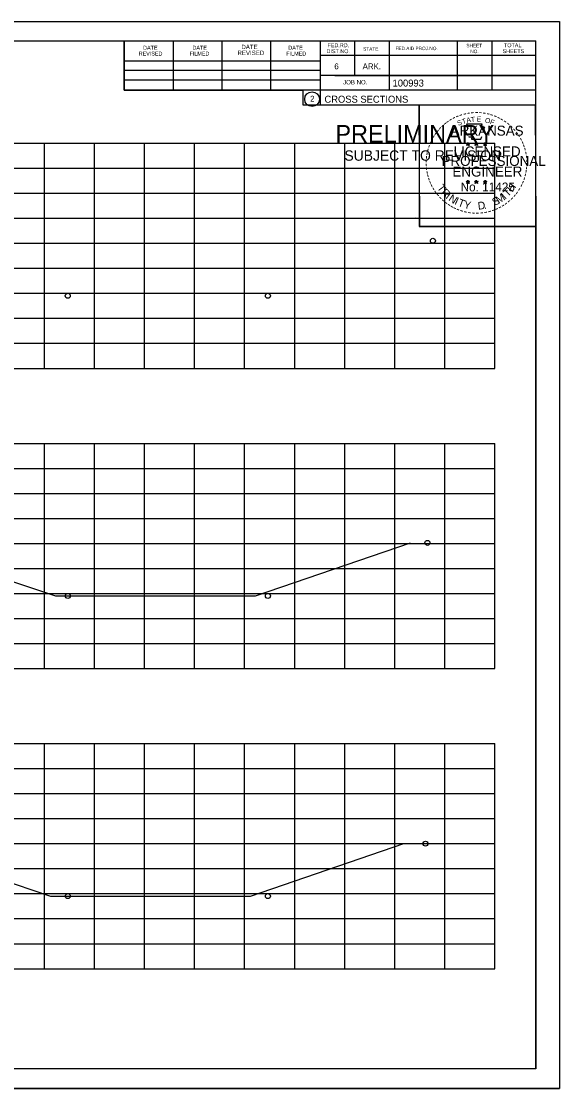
# Model space of a CAD drawing. Extents: x 4667 to 1632277, y -2100 to 724501.
# Drawn here: x 6194.9 to 6302.5, y -1537.1 to -1323.8 of the extents above; entities that cross this region are included whole.
import ezdxf

# ---------------------------------------------------------------- set-up
doc = ezdxf.new("R2010")
doc.units = 0
for name, color, linetype in [('R_Grid', 7, 'Continuous'), ('R_No Plot', 7, 'Continuous'), ('R_Water', 7, 'Continuous')]:
    doc.layers.add(name, color=color, linetype=linetype)

msp = doc.modelspace()

# ---------------------------------------------------------------- linework, layer by layer
at = {"layer": 'R_Grid'}
for p, q in [((5989.52, -1348.11), (6289.52, -1348.11)), ((6199.52, -1393.11), (6199.52, -1348.11)), ((6209.52, -1393.11), (6209.52, -1348.11)), ((6219.52, -1393.11), (6219.52, -1348.11)), ((6229.52, -1393.11), (6229.52, -1348.11)), ((6239.52, -1393.11), (6239.52, -1348.11)), ((6249.52, -1393.11), (6249.52, -1348.11)), ((6259.52, -1393.11), (6259.52, -1348.11)), ((6269.52, -1393.11), (6269.52, -1348.11)), ((6279.52, -1393.11), (6279.52, -1348.11)), ((6289.52, -1393.11), (6289.52, -1348.11)), ((5989.52, -1353.11), (6289.52, -1353.11)), ((5989.52, -1358.11), (6289.52, -1358.11)), ((5989.52, -1363.11), (6289.52, -1363.11)), ((5989.52, -1368.11), (6289.52, -1368.11)), ((5989.52, -1373.11), (6289.52, -1373.11)), ((5989.52, -1378.11), (6289.52, -1378.11)), ((5989.52, -1383.11), (6289.52, -1383.11)), ((5989.52, -1388.11), (6289.52, -1388.11)), ((5989.52, -1393.11), (6289.52, -1393.11)), ((5989.52, -1408.11), (6289.52, -1408.11)), ((6199.52, -1453.11), (6199.52, -1408.11)), ((6209.52, -1453.11), (6209.52, -1408.11)), ((6219.52, -1453.11), (6219.52, -1408.11)), ((6229.52, -1453.11), (6229.52, -1408.11)), ((6239.52, -1453.11), (6239.52, -1408.11)), ((6249.52, -1453.11), (6249.52, -1408.11)), ((6259.52, -1453.11), (6259.52, -1408.11)), ((6269.52, -1453.11), (6269.52, -1408.11)), ((6279.52, -1453.11), (6279.52, -1408.11)), ((6289.52, -1453.11), (6289.52, -1408.11)), ((5989.52, -1413.11), (6289.52, -1413.11)), ((5989.52, -1418.11), (6289.52, -1418.11)), ((5989.52, -1423.11), (6289.52, -1423.11)), ((5989.52, -1428.11), (6289.52, -1428.11)), ((5989.52, -1433.11), (6289.52, -1433.11)), ((5989.52, -1438.11), (6289.52, -1438.11)), ((5989.52, -1443.11), (6289.52, -1443.11)), ((5989.52, -1448.11), (6289.52, -1448.11)), ((5989.52, -1453.11), (6289.52, -1453.11)), ((5989.52, -1468.11), (6289.52, -1468.11)), ((6199.52, -1513.11), (6199.52, -1468.11)), ((6209.52, -1513.11), (6209.52, -1468.11)), ((6219.52, -1513.11), (6219.52, -1468.11)), ((6229.52, -1513.11), (6229.52, -1468.11)), ((6239.52, -1513.11), (6239.52, -1468.11)), ((6249.52, -1513.11), (6249.52, -1468.11)), ((6259.52, -1513.11), (6259.52, -1468.11)), ((6269.52, -1513.11), (6269.52, -1468.11)), ((6279.52, -1513.11), (6279.52, -1468.11)), ((6289.52, -1513.11), (6289.52, -1468.11)), ((5989.52, -1473.11), (6289.52, -1473.11)), ((5989.52, -1478.11), (6289.52, -1478.11)), ((5989.52, -1483.11), (6289.52, -1483.11)), ((5989.52, -1488.11), (6289.52, -1488.11)), ((5989.52, -1493.11), (6289.52, -1493.11)), ((5989.52, -1498.11), (6289.52, -1498.11)), ((5989.52, -1503.11), (6289.52, -1503.11)), ((5989.52, -1508.11), (6289.52, -1508.11)), ((5989.52, -1513.11), (6289.52, -1513.11))]:
    msp.add_line(p, q, dxfattribs=at)
at = {"layer": 'R_No Plot'}
for p, q in [((5969.12, -1323.75), (6302.46, -1323.75)), ((5981.52, -1327.65), (6297.7, -1327.65)), ((6215.44, -1337.53), (6215.44, -1327.65)), ((6225.3, -1337.53), (6225.3, -1327.85)), ((6235.06, -1337.53), (6235.06, -1327.85)), ((6244.74, -1337.53), (6244.74, -1327.85)), ((6254.6, -1327.65), (6254.6, -1340.45)), ((6261.44, -1327.65), (6261.44, -1334.59)), ((6268.38, -1327.65), (6268.38, -1337.53)), ((6281.96, -1327.65), (6281.96, -1337.53)), ((6288.9, -1327.65), (6288.9, -1337.53)), ((6297.7, -1533.11), (6297.7, -1327.65)), ((6297.7, -1330.59), (6254.6, -1330.59)), ((6297.7, -1330.57), (6297.7, -1330.57)), ((6215.44, -1331.67), (6254.6, -1331.67)), ((6215.44, -1333.53), (6254.6, -1333.53)), ((6215.44, -1337.53), (6215.44, -1335.47)), ((6215.44, -1335.47), (6254.6, -1335.47)), ((6297.7, -1334.59), (6254.6, -1334.59)), ((6257.56, -1334.59), (6297.7, -1334.59)), ((6297.7, -1337.53), (6215.44, -1337.53)), ((6254.6, -1340.45), (6297.7, -1340.45)), ((6283.79, -1348.19), (6284.14, -1348.3)), ((6283.79, -1348.19), (6284.04, -1348.24)), ((6283.79, -1348.19), (6284.03, -1348.31)), ((6284.14, -1347.94), (6284.1, -1348.19)), ((6284.14, -1348.3), (6284.14, -1347.94)), ((6284.14, -1347.94), (6284.19, -1348.19)), ((6284.49, -1348.19), (6284.14, -1348.3)), ((6284.49, -1348.19), (6284.2, -1348.24)), ((6284.49, -1348.19), (6284.28, -1348.29)), ((6285.46, -1348.19), (6285.81, -1348.3)), ((6285.46, -1348.19), (6285.71, -1348.24)), ((6285.46, -1348.19), (6285.7, -1348.31)), ((6285.81, -1347.94), (6285.77, -1348.19)), ((6285.81, -1348.3), (6285.81, -1347.94)), ((6285.81, -1347.94), (6285.86, -1348.19)), ((6286.16, -1348.19), (6285.81, -1348.3)), ((6286.16, -1348.19), (6285.87, -1348.24)), ((6286.16, -1348.19), (6285.95, -1348.29)), ((6287.22, -1348.2), (6287.57, -1348.31)), ((6287.22, -1348.2), (6287.48, -1348.25)), ((6287.22, -1348.2), (6287.46, -1348.33)), ((6287.57, -1347.95), (6287.53, -1348.2)), ((6287.57, -1348.31), (6287.57, -1347.95)), ((6287.57, -1347.95), (6287.62, -1348.2)), ((6287.92, -1348.2), (6287.57, -1348.31)), ((6287.92, -1348.2), (6287.63, -1348.25)), ((6287.92, -1348.2), (6287.72, -1348.31)), ((6283.92, -1348.6), (6284.14, -1348.3)), ((6283.92, -1348.6), (6284.05, -1348.36)), ((6283.92, -1348.6), (6284.14, -1348.38)), ((6284.35, -1348.6), (6284.14, -1348.3)), ((6284.35, -1348.6), (6284.14, -1348.39)), ((6284.35, -1348.6), (6284.21, -1348.31)), ((6285.59, -1348.6), (6285.81, -1348.3)), ((6285.59, -1348.6), (6285.72, -1348.36)), ((6285.59, -1348.6), (6285.81, -1348.38)), ((6286.02, -1348.6), (6285.81, -1348.3)), ((6286.02, -1348.6), (6285.81, -1348.39)), ((6286.02, -1348.6), (6285.88, -1348.31)), ((6287.36, -1348.61), (6287.57, -1348.31)), ((6287.36, -1348.61), (6287.48, -1348.37)), ((6287.36, -1348.61), (6287.57, -1348.39)), ((6287.79, -1348.61), (6287.57, -1348.31)), ((6287.79, -1348.61), (6287.57, -1348.4)), ((6287.79, -1348.61), (6287.65, -1348.32)), ((6283.79, -1355.76), (6284.13, -1355.88)), ((6283.79, -1355.76), (6284.04, -1355.81)), ((6283.79, -1355.76), (6284.02, -1355.89)), ((6283.92, -1356.17), (6284.13, -1355.88)), ((6283.92, -1356.17), (6284.04, -1355.93)), ((6283.92, -1356.17), (6284.13, -1355.96)), ((6284.13, -1355.51), (6284.09, -1355.76)), ((6284.13, -1355.88), (6284.13, -1355.51)), ((6284.13, -1355.51), (6284.18, -1355.76)), ((6284.48, -1355.76), (6284.13, -1355.88)), ((6284.35, -1356.17), (6284.13, -1355.88)), ((6284.35, -1356.17), (6284.13, -1355.96)), ((6284.48, -1355.76), (6284.2, -1355.81)), ((6284.35, -1356.17), (6284.21, -1355.88)), ((6284.48, -1355.76), (6284.28, -1355.87)), ((6285.45, -1355.76), (6285.8, -1355.88)), ((6285.45, -1355.76), (6285.71, -1355.81)), ((6285.45, -1355.76), (6285.69, -1355.89)), ((6285.59, -1356.17), (6285.8, -1355.88)), ((6285.59, -1356.17), (6285.71, -1355.93)), ((6285.59, -1356.17), (6285.8, -1355.96)), ((6285.8, -1355.51), (6285.76, -1355.76)), ((6285.8, -1355.88), (6285.8, -1355.51)), ((6285.8, -1355.51), (6285.85, -1355.76)), ((6286.15, -1355.76), (6285.8, -1355.88)), ((6286.02, -1356.17), (6285.8, -1355.88)), ((6286.02, -1356.17), (6285.8, -1355.96)), ((6286.15, -1355.76), (6285.86, -1355.81)), ((6286.02, -1356.17), (6285.88, -1355.88)), ((6286.15, -1355.76), (6285.95, -1355.87)), ((6287.22, -1355.77), (6287.57, -1355.89)), ((6287.22, -1355.77), (6287.47, -1355.82)), ((6287.22, -1355.77), (6287.46, -1355.9)), ((6287.35, -1356.18), (6287.57, -1355.89)), ((6287.35, -1356.18), (6287.48, -1355.94)), ((6287.35, -1356.18), (6287.57, -1355.97)), ((6287.57, -1355.52), (6287.53, -1355.77)), ((6287.57, -1355.89), (6287.57, -1355.52)), ((6287.57, -1355.52), (6287.62, -1355.77)), ((6287.92, -1355.77), (6287.57, -1355.89)), ((6287.78, -1356.18), (6287.57, -1355.89)), ((6287.78, -1356.18), (6287.57, -1355.97)), ((6287.92, -1355.77), (6287.63, -1355.82)), ((6287.78, -1356.18), (6287.65, -1355.89)), ((6287.92, -1355.77), (6287.71, -1355.88)), ((6273.74, -1362.9), (6273.74, -1362.9)), ((6297.7, -1533.11), (5981.52, -1533.11)), ((5969.12, -1537.09), (6302.46, -1537.09))]:
    msp.add_line(p, q, dxfattribs=at)
for points in [[(5969.12, -1323.75), (6302.46, -1323.75), (6302.46, -1537.09), (5969.12, -1537.09)], [(6215.44, -1327.65), (6215.44, -1337.53), (6251.18, -1337.53), (6251.18, -1340.45), (6274.38, -1340.45), (6274.38, -1364.78), (6297.7, -1364.78), (6297.7, -1533.11), (5981.52, -1533.11), (5981.52, -1327.65)], [(6274.38, -1340.45), (6297.58, -1340.45), (6297.7, -1364.78), (6274.5, -1364.78)]]:
    msp.add_lwpolyline(points, close=True, dxfattribs=at)
for points in [[(6283.83, -1344.31), (6284.1, -1345.14)], [(6287.34, -1345.24), (6287.48, -1344.95), (6286.8, -1344.98), (6286.95, -1344.31), (6283.83, -1344.31)], [(6284.14, -1347.94), (6284.35, -1348.6), (6283.79, -1348.19), (6284.49, -1348.19), (6283.92, -1348.6), (6284.14, -1347.94)], [(6284.32, -1346.74), (6284.32, -1346.82), (6284.89, -1346.84), (6284.83, -1347.32), (6286.7, -1347.32), (6286.9, -1346.78)], [(6285.81, -1347.94), (6286.02, -1348.6), (6285.46, -1348.19), (6286.16, -1348.19), (6285.59, -1348.6), (6285.81, -1347.94)], [(6287.57, -1347.95), (6287.79, -1348.61), (6287.22, -1348.2), (6287.92, -1348.2), (6287.36, -1348.61), (6287.57, -1347.95)], [(6284.13, -1355.51), (6284.35, -1356.17), (6283.79, -1355.76), (6284.48, -1355.76), (6283.92, -1356.17), (6284.13, -1355.51)], [(6285.8, -1355.51), (6286.02, -1356.17), (6285.45, -1355.76), (6286.15, -1355.76), (6285.59, -1356.17), (6285.8, -1355.51)], [(6287.57, -1355.52), (6287.78, -1356.18), (6287.22, -1355.77), (6287.92, -1355.77), (6287.35, -1356.18), (6287.57, -1355.52)]]:
    msp.add_lwpolyline(points, dxfattribs=at)
for centre, radius in [((6252.99, -1339.31), 1.47), ((6284.14, -1348.3), 0.172), ((6284.14, -1348.3), 0.145), ((6284.14, -1348.3), 0.116), ((6284.14, -1348.3), 0.0991), ((6284.14, -1348.3), 0.0747), ((6284.14, -1348.3), 0.0495), ((6284.14, -1348.3), 0.0296), ((6285.81, -1348.3), 0.172), ((6285.81, -1348.3), 0.145), ((6285.81, -1348.3), 0.116), ((6285.81, -1348.3), 0.0991), ((6285.81, -1348.3), 0.0747), ((6285.81, -1348.3), 0.0495), ((6285.81, -1348.3), 0.0296), ((6287.57, -1348.32), 0.172), ((6287.57, -1348.32), 0.145), ((6287.57, -1348.32), 0.116), ((6287.57, -1348.32), 0.0991), ((6287.57, -1348.32), 0.0747), ((6287.57, -1348.32), 0.0495), ((6287.57, -1348.32), 0.0296), ((6284.13, -1355.88), 0.172), ((6284.13, -1355.88), 0.145), ((6284.13, -1355.88), 0.116), ((6284.13, -1355.88), 0.0991), ((6284.13, -1355.88), 0.0747), ((6284.13, -1355.88), 0.0495), ((6284.13, -1355.88), 0.0296), ((6285.8, -1355.88), 0.172), ((6285.8, -1355.88), 0.145), ((6285.8, -1355.88), 0.116), ((6285.8, -1355.88), 0.0991), ((6285.8, -1355.88), 0.0747), ((6285.8, -1355.88), 0.0495), ((6285.8, -1355.88), 0.0296), ((6287.57, -1355.89), 0.172), ((6287.57, -1355.89), 0.145), ((6287.57, -1355.89), 0.116), ((6287.57, -1355.89), 0.0991), ((6287.57, -1355.89), 0.0747), ((6287.57, -1355.89), 0.0495), ((6287.57, -1355.89), 0.0296), ((6277.14, -1367.62), 0.5), ((6204.18, -1378.61), 0.5), ((6244.18, -1378.61), 0.5), ((6276.03, -1427.99), 0.5), ((6204.18, -1438.61), 0.5), ((6244.18, -1438.61), 0.5), ((6275.66, -1488.12), 0.5), ((6204.18, -1498.61), 0.5), ((6244.18, -1498.61), 0.5)]:
    msp.add_circle(centre, radius, dxfattribs=at)
at = {"layer": 'R_Water'}
for p, q in [((6168.34, -1427.48), (6201.72, -1438.61)), ((6167.97, -1487.48), (6200.71, -1498.61))]:
    msp.add_line(p, q, dxfattribs=at)
for points in [[(6201.72, -1438.61), (6241.72, -1438.61), (6272.69, -1427.97)], [(6200.71, -1498.61), (6240.71, -1498.61), (6271.36, -1488.08)]]:
    msp.add_lwpolyline(points, dxfattribs=at)

# ---------------------------------------------------------------- texts
at = {"layer": 'R_No Plot'}
for s, height, rotation, p in [('DATE', 0.782, 360, (6219.24, -1329.41)), ('DATE', 0.782, 360, (6229.1, -1329.41)), ('DATE', 0.879, 360, (6238.88, -1329.31)), ('DATE', 0.782, 360, (6248.26, -1329.41)), ('FED.RD.', 0.782, 360, (6256.08, -1328.93)), ('STATE', 0.684, 360, (6263.2, -1329.61)), ('FED.AID PROJ.NO.', 0.684, 360, (6269.66, -1329.51)), ('SHEET', 0.684, 360, (6283.82, -1328.93)), ('TOTAL', 0.782, 360, (6291.34, -1328.93)), ('REVISED', 0.782, 360, (6218.36, -1330.59)), ('FILMED', 0.782, 360, (6228.52, -1330.59)), ('REVISED', 0.879, 360, (6238.1, -1330.49)), ('FILMED', 0.782, 360, (6247.86, -1330.59)), ('DIST.NO.', 0.782, 360, (6255.88, -1330.11)), ('NO.', 0.684, 360, (6284.6, -1330.11)), ('SHEETS', 0.782, 360, (6291.06, -1330.11)), ('6', 1.17, 360, (6257.44, -1333.33)), ('ARK.', 1.172, 360, (6263.1, -1333.33)), ('JOB NO.', 0.879, 360, (6259.2, -1336.35)), ('100993', 1.4, 360, (6269.08, -1336.79)), ('2', 1.17, 360, (6252.61, -1339.8)), ('CROSS SECTIONS', 1.4, 360, (6255.47, -1340.02)), ('-', 1.6, 0.1862, (6285.51, -1342.6)), ('-', 1.6, 38.9507, (6279.66, -1344.92)), ('-', 1.6, 36.2317, (6280.14, -1344.54)), ('-', 1.6, 34.0636, (6280.71, -1344.14)), ('-', 1.6, 28.7918, (6281.31, -1343.77)), ('-', 1.6, 24.3072, (6281.94, -1343.46)), ('S', 1, 21.594, (6282.18, -1344.64)), ('-', 1.6, 19.1761, (6282.58, -1343.19)), ('T', 1, 16.4036, (6283.1, -1344.3)), ('-', 1.6, 13.6301, (6283.33, -1342.95)), ('A', 1, 11.2132, (6283.92, -1344.05)), ('-', 1.6, 10.2193, (6284.01, -1342.78)), ('T', 1, 6.0228, (6284.77, -1343.89)), ('-', 1.6, 5.8968, (6284.73, -1342.67)), ('E', 1, 0.8323, (6285.88, -1343.78)), ('-', 1.6, 357.743, (6286.23, -1342.61)), ('-', 1.6, 352.1617, (6286.97, -1342.67)), ('O', 1, 350.4515, (6287.48, -1343.99)), ('-', 1.6, 347.2049, (6287.69, -1342.78)), ('F', 1, 340.0707, (6288.44, -1344.22)), ('-', 1.6, 342.3362, (6288.33, -1342.94)), ('-', 1.6, 337.8551, (6289.06, -1343.16)), ('-', 1.6, 334.1211, (6289.69, -1343.43)), ('-', 1.6, 329.6409, (6290.27, -1343.72)), ('-', 1.6, 325.8627, (6290.92, -1344.08)), ('-', 1.6, 320.5297, (6291.53, -1344.5)), ('PRELIMINARY', 3.5, 360, (6257.66, -1347.98)), ('DWB', 0.01, 360, (6258.4, -1346.13)), ('-', 1.6, 54.2325, (6277.96, -1346.86)), ('-', 1.6, 50.6142, (6278.38, -1346.3)), ('-', 1.6, 48.423, (6278.78, -1345.81)), ('-', 1.6, 42.9622, (6279.23, -1345.33)), ('ARKANSAS', 2, 360, (6280.68, -1346.6)), ('-', 1.6, 315.5786, (6292.12, -1344.99)), ('-', 1.6, 309.8797, (6292.69, -1345.54)), ('-', 1.6, 306.6522, (6293.22, -1346.14)), ('-', 1.6, 67.7743, (6277.07, -1348.62)), ('-', 1.6, 62.8713, (6277.32, -1348)), ('-', 1.6, 58.0706, (6277.64, -1347.39)), ('-', 1.4, 303.6753, (6293.7, -1346.71)), ('-', 1.6, 299.6684, (6294.02, -1347.32)), ('-', 1.6, 294.6628, (6294.35, -1347.93)), ('SUBJECT TO REVISION', 2.0751, 360, (6259.46, -1351.61)), ('-', 1.6, 81.2013, (6276.52, -1350.67)), ('-', 1.6, 75.461, (6276.65, -1349.96)), ('-', 1.6, 72.3945, (6276.85, -1349.25)), ('LICENSED', 2, 360, (6281.28, -1350.75)), ('DWB', 0.01, 360, (6284.13, -1348.31)), ('DWB', 0.01, 360, (6285.8, -1348.31)), ('DWB', 0.01, 360, (6287.56, -1348.32)), ('-', 1.6, 290.5728, (6294.6, -1348.51)), ('-', 1.6, 285.1233, (6294.84, -1349.09)), ('-', 1.6, 280.5493, (6295.04, -1349.83)), ('-', 1.6, 94.1959, (6276.45, -1352.79)), ('-', 1.6, 89.0622, (6276.42, -1352.06)), ('-', 1.6, 85.1863, (6276.44, -1351.36)), ('PROFESSIONAL', 2, 360, (6278.86, -1352.65)), ('-', 1.6, 276.5962, (6295.2, -1350.6)), ('-', 1.6, 274.3301, (6295.26, -1351.32)), ('-', 1.6, 269.9407, (6295.29, -1351.95)), ('-', 1.6, 98.9479, (6276.52, -1353.46)), ('-', 1.6, 101.7149, (6276.66, -1354.19)), ('-', 1.6, 105.4578, (6276.82, -1354.78)), ('ENGINEER', 2, 360, (6281.04, -1354.78)), ('-', 1.6, 255.7626, (6295.09, -1353.95)), ('-', 1.6, 260.9953, (6295.2, -1353.27)), ('-', 1.6, 263.5172, (6295.28, -1352.62)), ('-', 1.6, 109.0874, (6277.04, -1355.42)), ('-', 1.6, 114.0643, (6277.29, -1356.01)), ('-', 1.6, 115.7289, (6277.59, -1356.63)), ('T', 1.54, 306.0406, (6277.89, -1357.04)), ('No. 11425', 1.757, 360, (6282.67, -1357.73)), ('DWB', 0.01, 360, (6284.12, -1355.88)), ('DWB', 0.01, 360, (6285.79, -1355.88)), ('DWB', 0.01, 360, (6287.56, -1355.89)), ('H', 1.54, 54.6088, (6293.01, -1358)), ('-', 1.6, 244.6197, (6294.43, -1355.97)), ('-', 1.6, 247.8887, (6294.69, -1355.34)), ('-', 1.6, 252.8681, (6294.91, -1354.67)), ('-', 1.6, 120.4471, (6277.95, -1357.22)), ('-', 1.6, 125.8934, (6278.35, -1357.78)), ('-', 1.6, 130.7181, (6278.82, -1358.33)), ('-', 1.6, 134.2238, (6279.33, -1358.87)), ('R', 1.54, 314.005, (6278.66, -1358.08)), ('I', 1.54, 321.9694, (6279.56, -1359.02)), ('N', 1.54, 326.5002, (6280.12, -1359.49)), ('I', 1.54, 335.3603, (6281.33, -1360.27)), ('S', 1.54, 26.9312, (6289.44, -1360.68)), ('M', 1.54, 32.6563, (6290.28, -1360.27)), ('I', 1.54, 42.1136, (6291.56, -1359.42)), ('T', 1.54, 46.6444, (6292.12, -1358.94)), ('-', 1.6, 225.7653, (6292.72, -1358.51)), ('-', 1.6, 231.2538, (6293.2, -1357.94)), ('-', 1.6, 233.8452, (6293.63, -1357.38)), ('-', 1.6, 239.0712, (6294.03, -1356.72)), ('-', 1.6, 138.9338, (6279.86, -1359.34)), ('-', 1.6, 144.6463, (6280.41, -1359.74)), ('-', 1.6, 148.0898, (6280.98, -1360.11)), ('-', 1.6, 151.5704, (6281.55, -1360.44)), ('-', 1.6, 154.6002, (6282.08, -1360.69)), ('T', 1.54, 339.8912, (6281.99, -1360.6)), ('Y', 1.54, 347.8556, (6283.21, -1361.05)), ('D', 1.54, 6.3969, (6286.19, -1361.41)), ('.', 1.54, 13.7642, (6287.39, -1361.28)), ('-', 1.6, 204.2516, (6289.94, -1360.54)), ('-', 1.6, 207.3568, (6290.56, -1360.22)), ('-', 1.6, 212.2491, (6291.12, -1359.87)), ('-', 1.6, 215.7363, (6291.65, -1359.49)), ('-', 1.6, 221.0851, (6292.2, -1359.02)), ('-', 1.6, 158.5612, (6282.7, -1360.94)), ('-', 1.6, 162.7983, (6283.39, -1361.15)), ('-', 1.6, 167.5555, (6284.1, -1361.32)), ('-', 1.6, 173.1155, (6284.87, -1361.43)), ('-', 1.6, 176.5183, (6285.62, -1361.48)), ('-', 1.6, 181.5918, (6286.37, -1361.46)), ('-', 1.6, 185.8167, (6287.18, -1361.39)), ('-', 1.6, 191.2858, (6287.91, -1361.25)), ('-', 1.6, 195.4743, (6288.64, -1361.05)), ('-', 1.6, 200.7184, (6289.32, -1360.81))]:
    msp.add_text(s, height=height, rotation=rotation, dxfattribs=at).set_placement(p)

doc.saveas('drawing.dxf')
